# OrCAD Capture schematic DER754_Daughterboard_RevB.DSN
size C; title: DER-740 DALI BOARD RevA
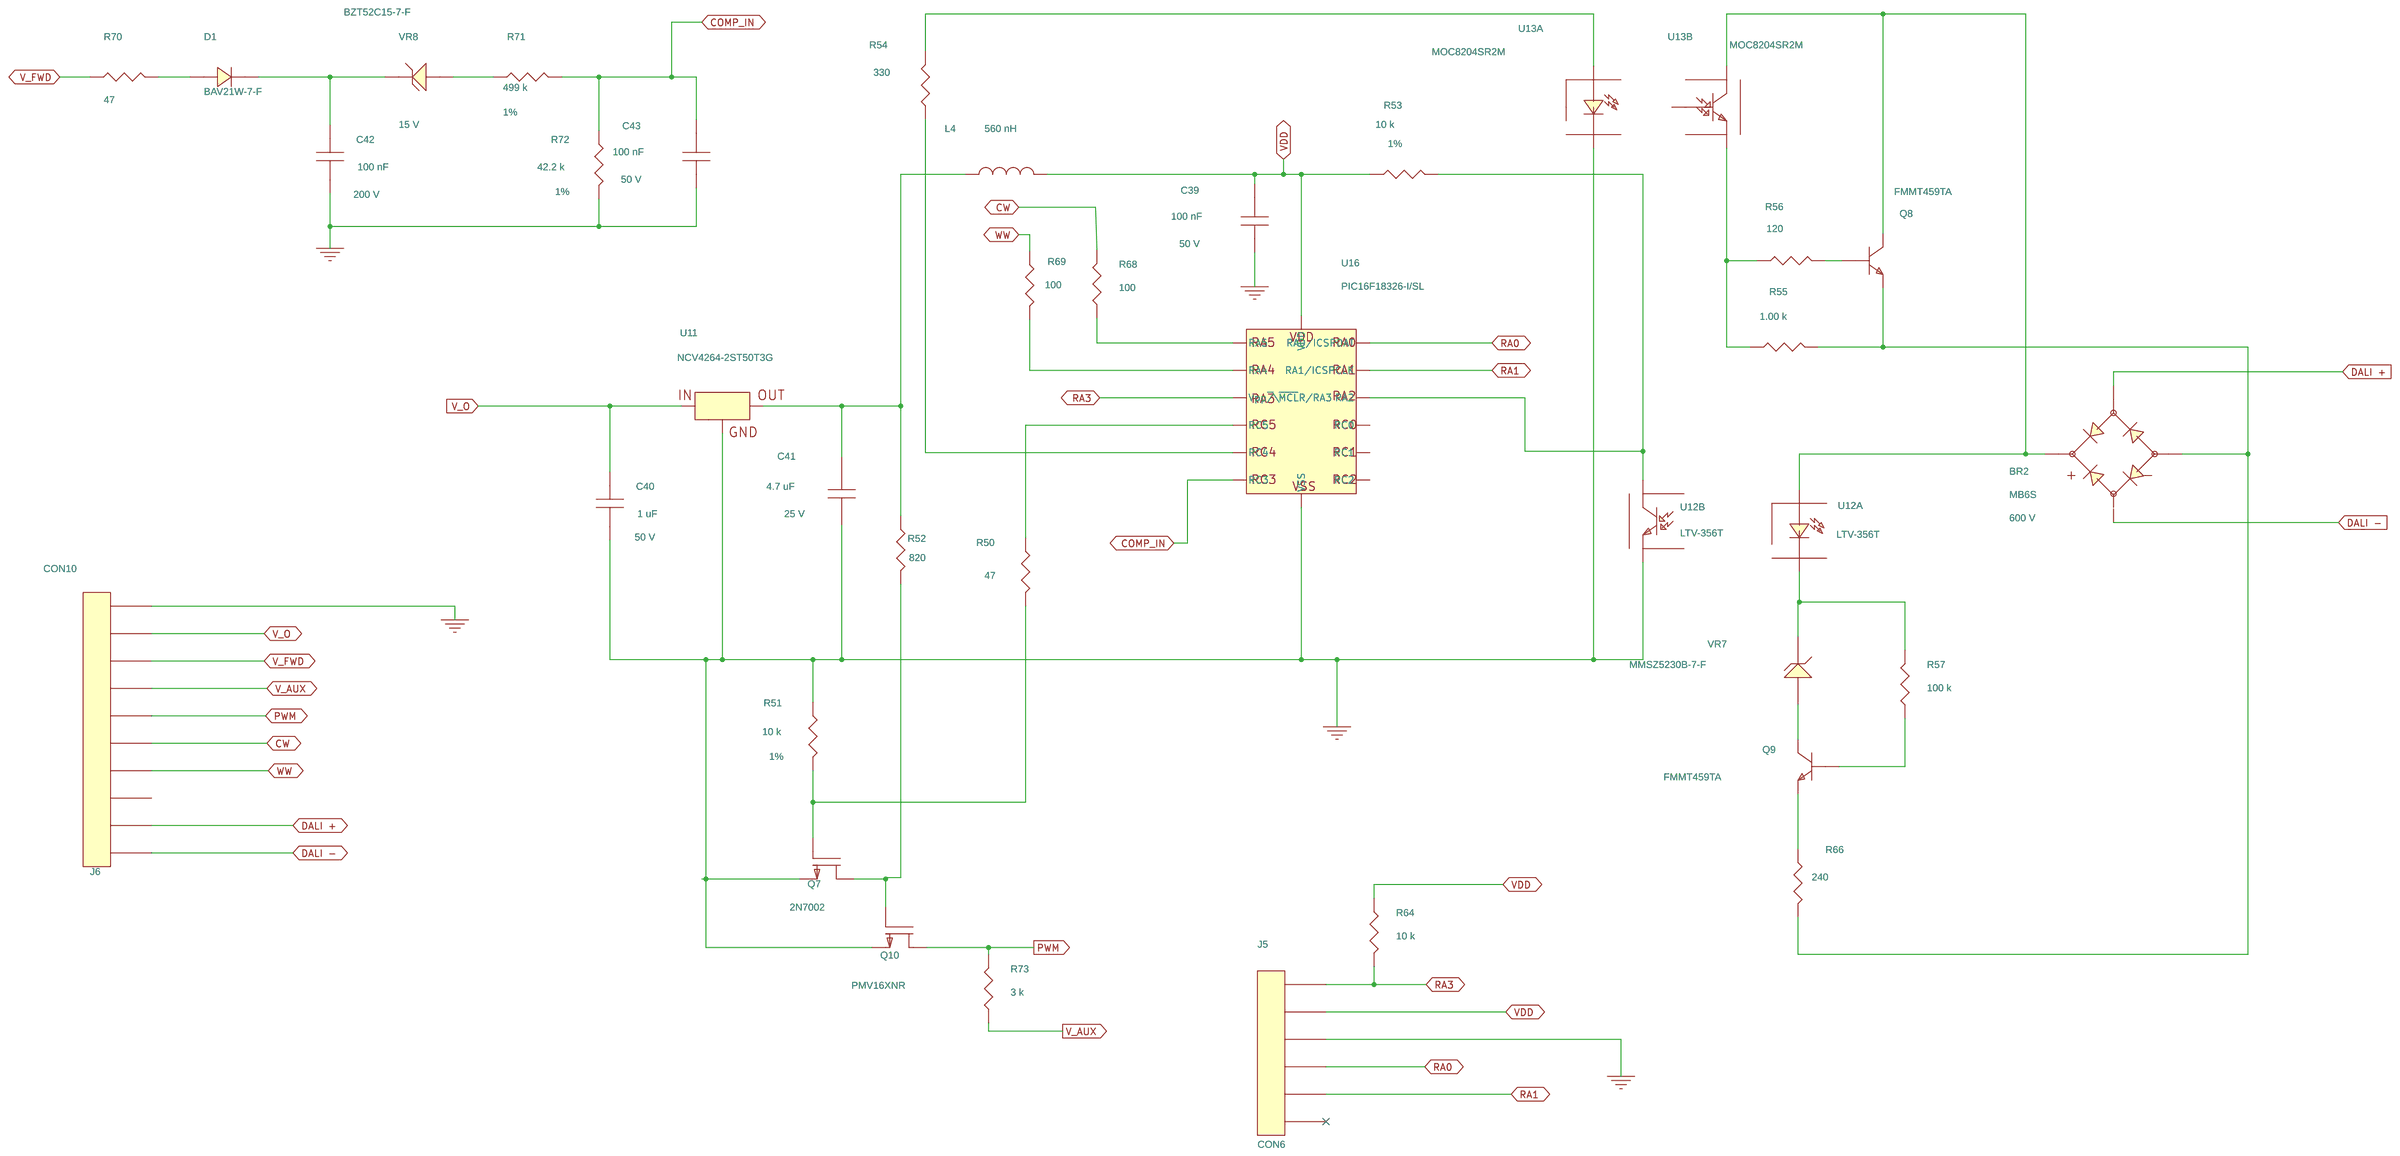
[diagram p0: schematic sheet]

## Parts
BR2  MB6S  [pismsoic4]
C39  100 nF  [pismc0805]
C40  1 uF  [pismc0805]
C41  4.7 uF  [pismc0805]
C42  100 nF  [pismc1206]
C43  100 nF  [pismc0805]
D1  BAV21W-7-F  [pi_sm_sod-123_12]
J5  CON6  [pi_molex_06_ra_22series]
J6  CON10  [pi_molex_10]
L4  560 nH  [pismindAISC0805]
Q7  2N7002  [pismsot23123_1]
Q8  FMMT459TA  [pismsot23123_1]
Q9  FMMT459TA  [pismsot23123_1]
Q10  PMV16XNR  [pismsot23123_1]
R50  47  [pismr0805]
R51  10 k  [pismr0805]
R52  820  [pismr0805]
R53  10 k  [pismr0805]
R54  330  [pismr0805]
R55  1.00 k  [pismr0805]
R56  120  [pismr0805]
R57  100 k  [pismr0805]
R64  10 k  [pismr0805]
R66  240  [pismr0603]
R68  100  [pismr0805]
R69  100  [pismr0805]
R70  47  [pismr0805]
R71  499 k  [pismr0805]
R72  42.2 k  [pismr0805]
R73  3 k  [pismr0805]
U11  NCV4264-2ST50T3G  [pi_sm_sot_223_1234]
U12  LTV-356T  [pi_4_smd_LTV356]  (sections A,B)
U13  MOC8204SR2M  [pi_6_smd]  (sections A,B)
U16  PIC16F18326-I/SL  [pisog05014wb300l400]
VR7  MMSZ5230B-7-F  [pi_sm_sod-123_12]
VR8  BZT52C15-7-F  [pi_sm_sod-123_12]

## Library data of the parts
BR2 = DIODE_BRIDGE_~~+-: ALT_SYMBOLS: pi_sm_soic4_slot; Disp_Voltage: 600 V; FPLIST: pismsoic4,pi_sm_soic4_slot; Part Number: 15-00498-00
C39 C43 = CAP_NP: Disp_Voltage: 50 V; Part Number: 20-00904-00; Voltage: 50 V
C40 = CAP_NP: Disp_Voltage: 50 V; Part Number: 20-09156-00; Voltage: 50 V
C41 = CAP_NP: Disp_Voltage: 25 V; Part Number: 20-09022-00; Voltage: 25 V
C42 = CAP_NP: Disp_Voltage: 200 V; Part Number: 20-00918-00; Voltage: 200 V
D1 = DIODE: Part Number: 15-00993-00
J5 = CON6: Part Number: 35-00226-00
J6 = CON10: Part Number: 35-00014-00
L4 = INDUCTOR: Part Number: 30-00479-00
Q7 = FET_N_GSD: Part Number: 50-00103-00
Q8 Q9 = NPN_BEC: Part Number: 55-00074-00
Q10 = FET_N_GSD: Part Number: 50-00229-00
R50 R70 = R: Part Number: 05-01487-00
R51 R53 = R: Disp_Tol: 1%; Part Number: 05-00684-00
R52 = R: Part Number: 05-01517-00
R54 = R: Part Number: 05-01507-00
R55 = R: Disp_Tol: 1%; Part Number: 05-03310-00
R56 = R: Part Number: 05-01497-00
R57 = R: Part Number: 05-01567-00
R64 = R: Part Number: 05-01543-00
R66 = R: Part Number: 05-01673-00
R68 R69 = R: Part Number: 05-01495-00
R71 = R: Disp_Tol: 1%; Part Number: 05-00847-00
R72 = R: Disp_Tol: 1%; Part Number: 05-00744-00
R73 = R: Part Number: 05-01530-00
U11 = NCV4264: Part Number: 45-04510-00
U12 = OPTO_A_B: Part Number: 53-00036-00
U13 = OPTO_A_B_Base: Part Number: 53-00035-00
U16 = PIC16F18326-I_SL: Part Number: 45-00497-00
VR7 = DIODE_ZENER: Part Number: 15-01080-00
VR8 = DIODE_ZENER: Disp_Voltage: 15 V; Part Number: 15-00923-00

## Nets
GND: C39.1 C40.2 C41.1 C42.2 C43.1 J5.3 J6.10 Q7.2(S) Q10.2(S) R51.1 R72.2 U11.2(GND) U12.3(E) U13.2(C) U16.14(VSS)
VDD: C39.2 J5.2 L4.2 R53.1 R64.1 U16.1(VDD)
COMP_IN: C43.2 R71.2 R72.1 U16.7(RC3)
CW: J6.5 R68.2
DALI +: BR2.1 J6.2
DALI -: BR2.2 J6.1
PWM: J6.6 Q10.3(D) R73.2
RA0: J5.4 U16.13(RA0/ICSPDAT)
RA1: J5.5 U16.12(RA1/ICSPCLK)
RA3: J5.1 R64.2 U16.4(Vpp~{/}\~{MCL}R/RA3)
V_AUX: J6.7 R73.1
V_FWD: J6.8 R70.1
V_O: C40.1 J6.9 U11.1(IN)
WW: J6.4 R69.1
N11807834: R54.2 U13.1(A)
N11807846: BR2.3 Q8.3(COLLECTOR) U12.1(A) U13.5(C)
N11807918: R55.1 R56.1 U13.4(E)
N11807964: Q8.1(BASE) R56.2
N11807986: BR2.4 Q8.2(EMITTER) R55.2 R66.2
N11807994: C41.2 L4.1 R52.1 U11.3(OUT)
N11807998: R53.2 U12.4(C) U16.11(RA2)
N11808486: R57.2 U12.2(C) VR7.1
N11808610: Q7.1(G) R50.2 R51.2
N11808638: Q7.3(D) Q10.1(G) R52.2
N11850613: R54.1 U16.6(RC4)
N11856301: R50.1 U16.5(RC5)
N11857036: Q9.3(COLLECTOR) VR7.2
N11857044: Q9.1(BASE) R57.1
N11857111: Q9.2(EMITTER) R66.1
N11914189: R68.1 U16.2(RA5)
N11914225: R69.2 U16.3(RA4)
N11915617: D1.2 R70.2
N11915634: C42.1 D1.1 VR8.1
N11915686: R71.1 VR8.2

Not connected (* = marked no-connect by the designer): J5 6*; J6 3; U11 4(GND4); U13 3(NC) 6(B); U16 8(RC2) 9(RC1) 10(RC0)
